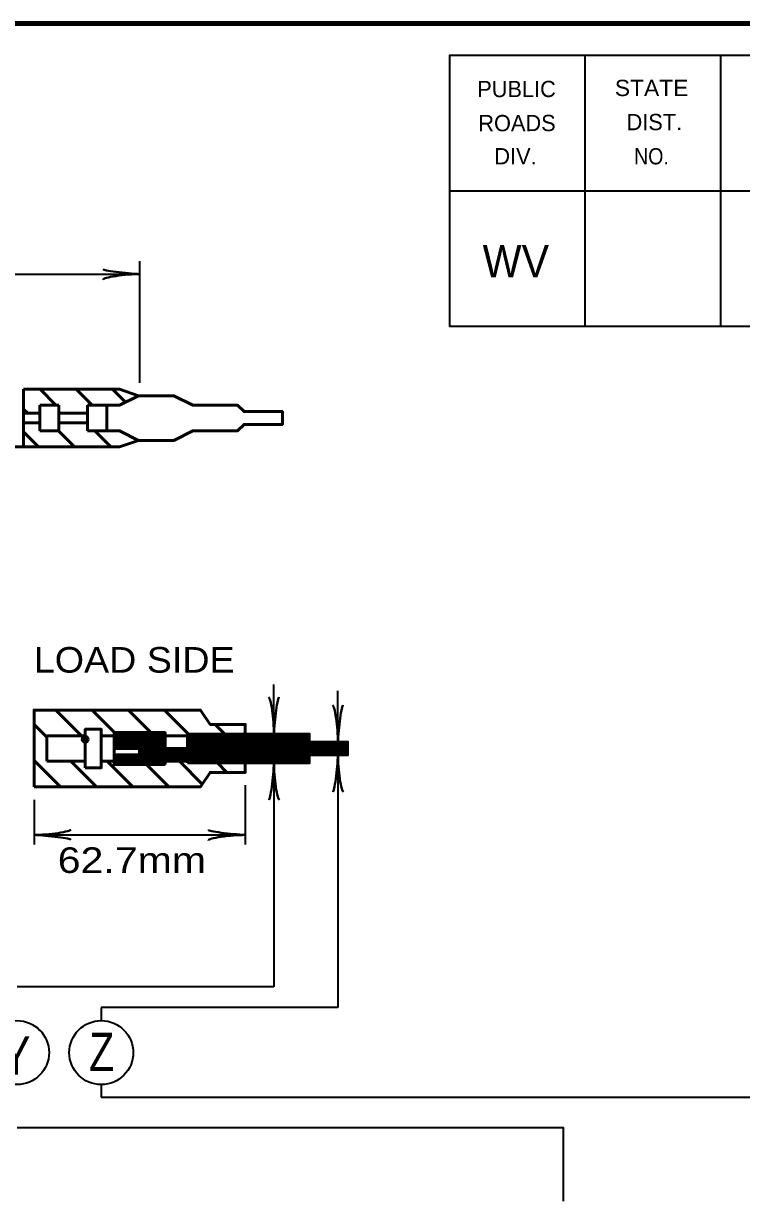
# Model space of a CAD drawing. Extents: x -32 to 824, y -6 to 538.
# Drawn here: x 637.3 to 704.6, y 421.3 to 531.7 of the extents above; entities that cross this region are included whole.
import ezdxf

# ---------------------------------------------------------------- set-up
doc = ezdxf.new("R2010")
doc.units = 0
doc.header["$LTSCALE"] = 1.1
doc.header["$PDMODE"] = 32
doc.header["$PDSIZE"] = 0.55
doc.layers.add('1', color=7, linetype='Continuous', lineweight=53)
doc.layers.add('61', color=7, linetype='Continuous', lineweight=35)

msp = doc.modelspace()

# ---------------------------------------------------------------- linework, layer by layer
at = {"layer": '1', "lineweight": 35}
for p, q in [((648.168, 498.051), (648.168, 509.451)), ((607.387, 508.251), (648.168, 508.251)), ((660.736, 465.123), (660.736, 469.773)), ((666.736, 464.373), (666.736, 469.173)), ((666.736, 463.173), (666.736, 439.473)), ((660.736, 462.423), (660.736, 441.423)), ((658.036, 460.323), (658.036, 454.773)), ((638.236, 458.973), (638.236, 454.773)), ((638.236, 455.673), (658.036, 455.673)), ((660.736, 441.423), (636.64, 441.423)), ((666.736, 439.473), (644.536, 439.473)), ((644.536, 439.473), (644.536, 438.256)), ((644.536, 432.256), (644.536, 431.073)), ((644.536, 431.073), (749.283, 431.073))]:
    msp.add_line(p, q, dxfattribs=at)
at = {"layer": '1'}
for p, q in [((637.248, 497.451), (646.264, 497.451)), ((637.26, 497.451), (637.26, 492.051)), ((640.287, 495.965), (638.802, 497.451)), ((643.696, 495.951), (642.196, 497.451)), ((646.809, 496.231), (645.59, 497.451)), ((646.264, 497.451), (648.045, 496.851)), ((638.764, 495.958), (638.764, 493.558)), ((638.764, 495.958), (640.564, 495.958)), ((640.564, 495.958), (640.564, 493.558)), ((643.264, 495.958), (643.264, 493.558)), ((643.264, 495.958), (646.264, 495.958)), ((646.264, 495.958), (648.045, 496.851)), ((648.045, 496.851), (651.345, 496.851)), ((657.325, 495.958), (657.925, 495.358)), ((637.651, 495.208), (637.258, 495.601)), ((637.26, 495.208), (638.764, 495.208)), ((640.564, 495.208), (643.264, 495.208)), ((657.925, 495.358), (661.525, 495.358)), ((661.525, 495.358), (661.525, 494.158)), ((637.26, 494.308), (638.764, 494.308)), ((640.564, 494.308), (643.264, 494.308)), ((657.325, 493.558), (657.925, 494.158)), ((657.925, 494.158), (661.525, 494.158)), ((638.649, 492.051), (637.269, 493.431)), ((638.764, 493.558), (640.564, 493.558)), ((642.043, 492.051), (640.527, 493.567)), ((643.264, 493.558), (646.264, 493.558)), ((645.437, 492.051), (643.937, 493.551)), ((646.264, 493.558), (648.045, 492.651)), ((648.045, 492.651), (646.264, 492.051)), ((648.045, 492.651), (651.345, 492.651)), ((653.125, 493.558), (657.325, 493.558)), ((630.187, 492.051), (637.275, 492.051)), ((646.264, 492.051), (637.275, 492.051)), ((642.693, 464.973), (640.293, 467.373)), ((645.787, 465.273), (643.687, 467.373)), ((649.182, 465.273), (647.082, 467.373)), ((652.726, 465.123), (650.476, 467.373)), ((639.436, 464.836), (638.236, 466.036)), ((639.436, 464.973), (639.436, 462.573)), ((639.436, 464.973), (643.036, 464.973)), ((644.536, 464.973), (645.736, 464.973)), ((645.736, 463.917), (645.736, 465.273)), ((645.736, 465.248), (645.761, 465.273)), ((645.736, 465.078), (645.931, 465.273)), ((645.736, 464.908), (646.101, 465.273)), ((645.736, 464.739), (646.27, 465.273)), ((645.736, 464.569), (646.44, 465.273)), ((645.736, 464.399), (646.61, 465.273)), ((645.736, 464.23), (646.779, 465.273)), ((645.736, 464.06), (646.949, 465.273)), ((645.736, 463.89), (647.119, 465.273)), ((647.213, 463.773), (645.736, 465.249)), ((647.043, 463.773), (645.736, 465.079)), ((645.788, 463.773), (647.288, 465.273)), ((647.383, 463.773), (645.883, 465.273)), ((645.958, 463.773), (647.458, 465.273)), ((647.552, 463.773), (646.052, 465.273)), ((646.128, 463.773), (647.628, 465.273)), ((647.722, 463.773), (646.222, 465.273)), ((646.298, 463.773), (647.798, 465.273)), ((647.892, 463.773), (646.392, 465.273)), ((646.467, 463.773), (647.967, 465.273)), ((648.061, 463.773), (646.561, 465.273)), ((646.637, 463.773), (648.137, 465.273)), ((649.731, 462.273), (646.731, 465.273)), ((646.807, 463.773), (648.307, 465.273)), ((649.901, 462.273), (646.901, 465.273)), ((646.976, 463.773), (648.476, 465.273)), ((650.07, 462.273), (647.07, 465.273)), ((647.146, 463.773), (648.646, 465.273)), ((650.24, 462.273), (647.24, 465.273)), ((647.316, 463.773), (648.816, 465.273)), ((647.343, 462.273), (650.343, 465.273)), ((650.41, 462.273), (647.41, 465.273)), ((647.486, 463.773), (648.986, 465.273)), ((647.513, 462.273), (650.513, 465.273)), ((650.536, 462.316), (647.58, 465.273)), ((647.655, 463.773), (649.155, 465.273)), ((647.683, 462.273), (650.536, 465.126)), ((650.536, 462.486), (647.749, 465.273)), ((647.825, 463.773), (649.325, 465.273)), ((647.852, 462.273), (650.536, 464.957)), ((650.536, 462.655), (647.919, 465.273)), ((647.995, 463.773), (649.495, 465.273)), ((650.536, 462.825), (648.089, 465.273)), ((648.136, 463.745), (649.664, 465.273)), ((648.136, 463.575), (649.834, 465.273)), ((648.136, 463.405), (650.004, 465.273)), ((648.136, 463.235), (650.173, 465.273)), ((650.536, 462.995), (648.258, 465.273)), ((650.536, 463.164), (648.428, 465.273)), ((650.536, 463.334), (648.598, 465.273)), ((650.536, 463.504), (648.767, 465.273)), ((650.536, 463.674), (648.937, 465.273)), ((650.536, 463.843), (649.107, 465.273)), ((650.536, 464.013), (649.277, 465.273)), ((650.536, 464.183), (649.446, 465.273)), ((650.536, 464.352), (649.616, 465.273)), ((650.536, 464.522), (649.786, 465.273)), ((650.536, 464.692), (649.955, 465.273)), ((650.536, 464.862), (650.125, 465.273)), ((650.536, 465.031), (650.295, 465.273)), ((650.536, 465.201), (650.465, 465.273)), ((650.536, 465.273), (650.536, 463.773)), ((650.536, 464.973), (652.636, 464.973)), ((652.636, 465.022), (652.737, 465.123)), ((652.636, 464.852), (652.907, 465.123)), ((652.636, 464.683), (653.076, 465.123)), ((652.636, 464.513), (653.246, 465.123)), ((652.636, 464.343), (653.416, 465.123)), ((652.636, 464.173), (653.585, 465.123)), ((652.636, 464.004), (653.755, 465.123)), ((652.636, 463.834), (653.925, 465.123)), ((652.636, 463.664), (654.095, 465.123)), ((652.636, 463.495), (654.264, 465.123)), ((652.636, 463.325), (654.434, 465.123)), ((652.636, 463.155), (654.604, 465.123)), ((652.636, 462.986), (654.773, 465.123)), ((652.636, 462.816), (654.943, 465.123)), ((652.636, 462.646), (655.113, 465.123)), ((652.636, 462.476), (655.282, 465.123)), ((655.177, 462.423), (652.636, 464.963)), ((655.346, 462.423), (652.646, 465.123)), ((652.752, 462.423), (655.452, 465.123)), ((655.516, 462.423), (652.816, 465.123)), ((652.922, 462.423), (655.622, 465.123)), ((655.686, 462.423), (652.986, 465.123)), ((653.091, 462.423), (655.792, 465.123)), ((655.855, 462.423), (653.155, 465.123)), ((653.261, 462.423), (655.961, 465.123)), ((656.025, 462.423), (653.325, 465.123)), ((653.431, 462.423), (656.131, 465.123)), ((656.195, 462.423), (653.495, 465.123)), ((653.601, 462.423), (656.301, 465.123)), ((656.364, 462.423), (653.664, 465.123)), ((653.77, 462.423), (656.47, 465.123)), ((656.534, 462.423), (653.834, 465.123)), ((653.94, 462.423), (656.64, 465.123)), ((656.704, 462.423), (654.004, 465.123)), ((654.11, 462.423), (656.81, 465.123)), ((656.874, 462.423), (654.174, 465.123)), ((654.279, 462.423), (656.98, 465.123)), ((657.043, 462.423), (654.343, 465.123)), ((654.449, 462.423), (657.149, 465.123)), ((657.213, 462.423), (654.513, 465.123)), ((654.619, 462.423), (657.319, 465.123)), ((657.383, 462.423), (654.683, 465.123)), ((654.789, 462.423), (657.489, 465.123)), ((657.552, 462.423), (654.852, 465.123)), ((654.958, 462.423), (657.658, 465.123)), ((657.722, 462.423), (655.022, 465.123)), ((655.128, 462.423), (657.828, 465.123)), ((657.892, 462.423), (655.192, 465.123)), ((656.12, 465.123), (655.22, 466.023)), ((655.298, 462.423), (657.998, 465.123)), ((658.062, 462.423), (655.361, 465.123)), ((655.467, 462.423), (658.167, 465.123)), ((658.231, 462.423), (655.531, 465.123)), ((655.637, 462.423), (658.337, 465.123)), ((658.401, 462.423), (655.701, 465.123)), ((655.807, 462.423), (658.507, 465.123)), ((658.571, 462.423), (655.871, 465.123)), ((655.976, 462.423), (658.677, 465.123)), ((658.74, 462.423), (656.04, 465.123)), ((656.146, 462.423), (658.846, 465.123)), ((658.91, 462.423), (656.21, 465.123)), ((656.316, 462.423), (659.016, 465.123)), ((659.08, 462.423), (656.38, 465.123)), ((656.486, 462.423), (659.186, 465.123)), ((659.249, 462.423), (656.549, 465.123)), ((656.655, 462.423), (659.355, 465.123)), ((659.419, 462.423), (656.719, 465.123)), ((656.825, 462.423), (659.525, 465.123)), ((659.589, 462.423), (656.889, 465.123)), ((656.995, 462.423), (659.695, 465.123)), ((659.759, 462.423), (657.058, 465.123)), ((657.164, 462.423), (659.865, 465.123)), ((659.928, 462.423), (657.228, 465.123)), ((657.334, 462.423), (660.034, 465.123)), ((660.098, 462.423), (657.398, 465.123)), ((657.504, 462.423), (660.204, 465.123)), ((660.268, 462.423), (657.568, 465.123)), ((657.674, 462.423), (660.374, 465.123)), ((660.437, 462.423), (657.737, 465.123)), ((657.843, 462.423), (660.543, 465.123)), ((660.607, 462.423), (657.907, 465.123)), ((658.013, 462.423), (660.713, 465.123)), ((660.777, 462.423), (658.077, 465.123)), ((658.183, 462.423), (660.883, 465.123)), ((660.947, 462.423), (658.247, 465.123)), ((658.352, 462.423), (661.052, 465.123)), ((661.116, 462.423), (658.416, 465.123)), ((658.522, 462.423), (661.222, 465.123)), ((661.286, 462.423), (658.586, 465.123)), ((658.692, 462.423), (661.392, 465.123)), ((661.456, 462.423), (658.756, 465.123)), ((658.861, 462.423), (661.562, 465.123)), ((661.625, 462.423), (658.925, 465.123)), ((659.031, 462.423), (661.731, 465.123)), ((661.795, 462.423), (659.095, 465.123)), ((659.201, 462.423), (661.901, 465.123)), ((661.965, 462.423), (659.265, 465.123)), ((659.371, 462.423), (662.071, 465.123)), ((662.134, 462.423), (659.434, 465.123)), ((659.54, 462.423), (662.24, 465.123)), ((662.304, 462.423), (659.604, 465.123)), ((659.71, 462.423), (662.41, 465.123)), ((662.474, 462.423), (659.774, 465.123)), ((659.88, 462.423), (662.58, 465.123)), ((662.644, 462.423), (659.944, 465.123)), ((660.05, 462.423), (662.75, 465.123)), ((662.813, 462.423), (660.113, 465.123)), ((660.219, 462.423), (662.919, 465.123)), ((662.983, 462.423), (660.283, 465.123)), ((660.389, 462.423), (663.089, 465.123)), ((663.153, 462.423), (660.453, 465.123)), ((660.559, 462.423), (663.259, 465.123)), ((663.322, 462.423), (660.622, 465.123)), ((660.728, 462.423), (663.428, 465.123)), ((663.492, 462.423), (660.792, 465.123)), ((660.898, 462.423), (663.598, 465.123)), ((663.662, 462.423), (660.962, 465.123)), ((661.068, 462.423), (663.768, 465.123)), ((663.832, 462.423), (661.132, 465.123)), ((661.237, 462.423), (663.937, 465.123)), ((664.001, 462.423), (661.301, 465.123)), ((661.407, 462.423), (664.036, 465.052)), ((664.036, 462.557), (661.471, 465.123)), ((664.036, 462.727), (661.641, 465.123)), ((664.036, 462.897), (661.81, 465.123)), ((664.036, 463.066), (661.98, 465.123)), ((664.1, 463.173), (662.15, 465.123)), ((664.269, 463.173), (662.319, 465.123)), ((664.439, 463.173), (662.489, 465.123)), ((664.609, 463.173), (662.659, 465.123)), ((664.779, 463.173), (662.829, 465.123)), ((664.948, 463.173), (662.998, 465.123)), ((665.118, 463.173), (663.168, 465.123)), ((664.036, 464.424), (663.338, 465.123)), ((664.036, 464.594), (663.507, 465.123)), ((664.036, 464.764), (663.677, 465.123)), ((664.036, 464.933), (663.847, 465.123)), ((664.036, 465.103), (664.017, 465.123)), ((646.873, 463.773), (645.736, 464.91)), ((646.704, 463.773), (645.736, 464.74)), ((646.534, 463.773), (645.736, 464.57)), ((646.364, 463.773), (645.736, 464.401)), ((646.195, 463.773), (645.736, 464.231)), ((646.025, 463.773), (645.736, 464.061)), ((645.855, 463.773), (645.736, 463.892)), ((648.022, 462.273), (650.536, 464.787)), ((648.192, 462.273), (650.536, 464.617)), ((648.361, 462.273), (650.536, 464.448)), ((648.531, 462.273), (650.536, 464.278)), ((648.701, 462.273), (650.536, 464.108)), ((648.87, 462.273), (650.536, 463.938)), ((655.007, 462.423), (652.636, 464.793)), ((654.837, 462.423), (652.636, 464.624)), ((654.667, 462.423), (652.636, 464.454)), ((654.498, 462.423), (652.636, 464.284)), ((654.328, 462.423), (652.636, 464.114)), ((654.158, 462.423), (652.636, 463.945)), ((661.577, 462.423), (664.036, 464.882)), ((661.747, 462.423), (664.036, 464.712)), ((661.916, 462.423), (664.036, 464.543)), ((662.086, 462.423), (664.036, 464.373)), ((662.256, 462.423), (664.206, 464.373)), ((662.425, 462.423), (664.375, 464.373)), ((662.595, 462.423), (664.545, 464.373)), ((662.765, 462.423), (664.715, 464.373)), ((662.935, 462.423), (664.885, 464.373)), ((663.104, 462.423), (665.054, 464.373)), ((663.274, 462.423), (665.224, 464.373)), ((665.288, 463.173), (664.088, 464.373)), ((664.194, 463.173), (665.394, 464.373)), ((665.457, 463.173), (664.257, 464.373)), ((664.363, 463.173), (665.563, 464.373)), ((665.627, 463.173), (664.427, 464.373)), ((664.533, 463.173), (665.733, 464.373)), ((665.797, 463.173), (664.597, 464.373)), ((664.703, 463.173), (665.903, 464.373)), ((665.966, 463.173), (664.767, 464.373)), ((664.872, 463.173), (666.072, 464.373)), ((666.136, 463.173), (664.936, 464.373)), ((665.042, 463.173), (666.242, 464.373)), ((666.306, 463.173), (665.106, 464.373)), ((665.212, 463.173), (666.412, 464.373)), ((666.476, 463.173), (665.276, 464.373)), ((665.382, 463.173), (666.582, 464.373)), ((666.645, 463.173), (665.445, 464.373)), ((665.551, 463.173), (666.751, 464.373)), ((666.815, 463.173), (665.615, 464.373)), ((665.721, 463.173), (666.921, 464.373)), ((666.985, 463.173), (665.785, 464.373)), ((665.891, 463.173), (667.091, 464.373)), ((667.154, 463.173), (665.954, 464.373)), ((666.06, 463.173), (667.26, 464.373)), ((667.324, 463.173), (666.124, 464.373)), ((666.23, 463.173), (667.43, 464.373)), ((667.494, 463.173), (666.294, 464.373)), ((666.4, 463.173), (667.6, 464.373)), ((667.636, 463.2), (666.464, 464.373)), ((666.57, 463.173), (667.636, 464.239)), ((667.636, 463.37), (666.633, 464.373)), ((666.739, 463.173), (667.636, 464.07)), ((667.636, 463.539), (666.803, 464.373)), ((666.909, 463.173), (667.636, 463.9)), ((667.636, 463.709), (666.973, 464.373)), ((667.636, 463.879), (667.142, 464.373)), ((667.636, 464.049), (667.312, 464.373)), ((667.636, 464.218), (667.482, 464.373)), ((645.736, 463.173), (645.736, 463.773)), ((645.736, 463.042), (645.867, 463.173)), ((645.736, 462.872), (646.037, 463.173)), ((645.736, 462.702), (646.207, 463.173)), ((645.736, 462.533), (646.376, 463.173)), ((645.736, 462.363), (646.546, 463.173)), ((646.507, 462.273), (645.736, 463.043)), ((646.337, 462.273), (645.736, 462.873)), ((646.676, 462.273), (645.776, 463.173)), ((645.816, 462.273), (646.716, 463.173)), ((646.846, 462.273), (645.946, 463.173)), ((645.986, 462.273), (646.885, 463.173)), ((647.016, 462.273), (646.116, 463.173)), ((646.155, 462.273), (647.055, 463.173)), ((647.185, 462.273), (646.285, 463.173)), ((646.325, 462.273), (647.225, 463.173)), ((647.355, 462.273), (646.455, 463.173)), ((646.495, 462.273), (647.395, 463.173)), ((647.525, 462.273), (646.625, 463.173)), ((646.664, 462.273), (647.564, 463.173)), ((647.695, 462.273), (646.795, 463.173)), ((646.834, 462.273), (647.734, 463.173)), ((647.864, 462.273), (646.964, 463.173)), ((647.004, 462.273), (647.904, 463.173)), ((648.034, 462.273), (647.134, 463.173)), ((647.173, 462.273), (648.073, 463.173)), ((648.204, 462.273), (647.304, 463.173)), ((648.373, 462.273), (647.473, 463.173)), ((648.543, 462.273), (647.643, 463.173)), ((648.713, 462.273), (647.813, 463.173)), ((648.883, 462.273), (647.983, 463.173)), ((649.561, 462.273), (648.136, 463.698)), ((649.392, 462.273), (648.136, 463.528)), ((649.222, 462.273), (648.136, 463.358)), ((649.052, 462.273), (648.136, 463.189)), ((649.04, 462.273), (650.536, 463.769)), ((649.21, 462.273), (650.536, 463.599)), ((649.38, 462.273), (650.536, 463.429)), ((649.549, 462.273), (650.536, 463.26)), ((649.719, 462.273), (650.536, 463.09)), ((649.889, 462.273), (650.536, 462.92)), ((650.058, 462.273), (650.536, 462.75)), ((650.536, 463.754), (650.555, 463.773)), ((650.536, 463.584), (650.725, 463.773)), ((650.536, 463.414), (650.895, 463.773)), ((650.536, 463.244), (651.064, 463.773)), ((650.536, 463.075), (651.234, 463.773)), ((650.536, 462.905), (651.404, 463.773)), ((650.536, 462.735), (651.574, 463.773)), ((651.568, 462.573), (650.536, 463.604)), ((651.398, 462.573), (650.536, 463.435)), ((651.229, 462.573), (650.536, 463.265)), ((651.059, 462.573), (650.536, 463.095)), ((650.889, 462.573), (650.536, 462.925)), ((650.719, 462.573), (650.536, 462.756)), ((651.738, 462.573), (650.538, 463.773)), ((650.543, 462.573), (651.743, 463.773)), ((651.907, 462.573), (650.707, 463.773)), ((650.713, 462.573), (651.913, 463.773)), ((652.077, 462.573), (650.877, 463.773)), ((650.883, 462.573), (652.083, 463.773)), ((652.247, 462.573), (651.047, 463.773)), ((651.052, 462.573), (652.252, 463.773)), ((652.416, 462.573), (651.216, 463.773)), ((651.222, 462.573), (652.422, 463.773)), ((652.586, 462.573), (651.386, 463.773)), ((651.392, 462.573), (652.592, 463.773)), ((652.636, 462.692), (651.556, 463.773)), ((651.562, 462.573), (652.636, 463.647)), ((652.636, 462.862), (651.726, 463.773)), ((651.731, 462.573), (652.636, 463.478)), ((652.636, 463.032), (651.895, 463.773)), ((651.901, 462.573), (652.636, 463.308)), ((652.636, 463.201), (652.065, 463.773)), ((652.071, 462.573), (652.636, 463.138)), ((652.636, 463.371), (652.235, 463.773)), ((652.24, 462.573), (652.636, 462.969)), ((652.636, 463.541), (652.404, 463.773)), ((652.41, 462.573), (652.636, 462.799)), ((652.636, 463.711), (652.574, 463.773)), ((653.989, 462.423), (652.636, 463.775)), ((652.636, 462.423), (652.636, 463.773)), ((653.819, 462.423), (652.636, 463.605)), ((653.649, 462.423), (652.636, 463.436)), ((653.479, 462.423), (652.636, 463.266)), ((653.31, 462.423), (652.636, 463.096)), ((653.14, 462.423), (652.636, 462.926)), ((652.97, 462.423), (652.636, 462.757)), ((663.444, 462.423), (664.036, 463.015)), ((663.613, 462.423), (664.036, 462.846)), ((667.079, 463.173), (667.636, 463.73)), ((667.248, 463.173), (667.636, 463.561)), ((667.418, 463.173), (667.636, 463.391)), ((667.588, 463.173), (667.636, 463.221)), ((640.705, 460.173), (638.236, 462.641)), ((639.436, 462.573), (643.036, 462.573)), ((644.099, 460.173), (641.699, 462.573)), ((644.536, 462.573), (645.736, 462.573)), ((647.493, 460.173), (645.093, 462.573)), ((646.167, 462.273), (645.736, 462.704)), ((645.998, 462.273), (645.736, 462.534)), ((645.828, 462.273), (645.736, 462.364)), ((650.887, 460.173), (648.787, 462.273)), ((650.228, 462.273), (650.536, 462.581)), ((650.398, 462.273), (650.536, 462.411)), ((650.55, 462.573), (650.536, 462.586)), ((650.536, 462.573), (650.536, 462.273)), ((654.014, 460.44), (651.882, 462.573)), ((652.58, 462.573), (652.636, 462.629)), ((652.801, 462.423), (652.636, 462.587)), ((656.326, 461.523), (655.426, 462.423)), ((663.783, 462.423), (664.036, 462.676)), ((663.953, 462.423), (664.036, 462.506))]:
    msp.add_line(p, q, dxfattribs=at)
at = {"layer": '1', "lineweight": 158}
msp.add_lwpolyline([(817.398, 531.744), (25.698, 531.644), (25.798, 5.644)], dxfattribs=at)
at = {"layer": '1'}
for points in [[(637.275, 492.051), (632.753, 492.051), (632.753, 495.958)], [(651.345, 496.851), (653.125, 495.958), (657.325, 495.958)], [(638.236, 460.173), (638.236, 467.373), (653.836, 467.373), (654.736, 466.023), (658.036, 466.023), (658.036, 465.123)], [(645.736, 463.173), (645.736, 463.773), (645.736, 465.273), (650.536, 465.273)], [(650.536, 462.273), (645.736, 462.273), (645.736, 463.173), (648.136, 463.173), (648.136, 463.773), (645.736, 463.773)], [(658.036, 462.423), (658.036, 461.523), (654.736, 461.523), (653.836, 460.173), (638.236, 460.173)]]:
    msp.add_lwpolyline(points, dxfattribs=at)
for points in [[(645.064, 493.558), (645.064, 495.958), (646.264, 495.958), (648.045, 496.851), (651.345, 496.851), (653.125, 495.958), (657.325, 495.958), (657.925, 495.358), (661.525, 495.358), (661.525, 494.158), (657.925, 494.158), (657.325, 493.558), (653.125, 493.558), (651.345, 492.651), (648.045, 492.651), (646.264, 493.558)], [(643.036, 461.973), (643.036, 465.573), (644.536, 465.573), (644.536, 461.973)], [(643.036, 461.973), (643.036, 465.573), (644.536, 465.573), (644.536, 461.973)], [(652.636, 462.423), (652.636, 462.573), (652.636, 463.773), (652.636, 465.123), (664.036, 465.123), (664.036, 464.373), (667.636, 464.373), (667.636, 463.173), (664.036, 463.173), (664.036, 462.423)], [(650.536, 462.573), (650.536, 463.773), (652.636, 463.773), (652.636, 462.573)]]:
    msp.add_lwpolyline(points, close=True, dxfattribs=at)
at = {"layer": '1', "lineweight": 35}
msp.add_lwpolyline([(636.64, 428.223), (687.841, 428.223), (687.841, 421.316)], dxfattribs=at)
for centre in [(636.64, 435.256), (644.536, 435.256)]:
    msp.add_circle(centre, 3, dxfattribs=at)
at = {"layer": '1', "lineweight": 40}
for centre, major_axis, ratio, start_param, end_param in [((646.858, 507.919), (2.143, 0.187), 0.122415, 0.8963533, 3.1415927), ((646.823, 508.505), (2.108, -0.211), 0.07063, 3.1407148, 5.41811), ((660.405, 466.432), (0.187, -2.143), 0.122415, 0.8963533, 3.1415927), ((660.405, 466.432), (0.187, -2.143), 0.122415, 0.8963533, 3.1415927), ((660.99, 466.467), (-0.211, -2.108), 0.07063, 3.1407148, 5.41811), ((660.99, 466.467), (-0.211, -2.108), 0.07063, 3.1407148, 5.41811), ((666.405, 465.682), (0.187, -2.143), 0.122415, 0.8963533, 3.1415927), ((666.99, 465.717), (-0.211, -2.108), 0.07063, 3.1407148, 5.41811), ((666.482, 461.828), (0.211, 2.108), 0.07063, 3.1407148, 5.41811), ((667.068, 461.863), (-0.187, 2.143), 0.122415, 0.8963533, 3.1415927), ((660.482, 461.078), (0.211, 2.108), 0.07063, 3.1407148, 5.41811), ((660.482, 461.078), (0.211, 2.108), 0.07063, 3.1407148, 5.41811), ((661.068, 461.113), (-0.187, 2.143), 0.122415, 0.8963533, 3.1415927), ((661.068, 461.113), (-0.187, 2.143), 0.122415, 0.8963533, 3.1415927), ((639.546, 456.004), (-2.143, -0.187), 0.122415, 0.8963533, 3.1415927), ((639.546, 456.004), (-2.143, -0.187), 0.122415, 0.8963533, 3.1415927), ((656.692, 455.927), (2.108, -0.211), 0.07063, 3.1407148, 5.41811), ((639.581, 455.419), (-2.108, 0.211), 0.07063, 3.1407148, 5.41811), ((639.581, 455.419), (-2.108, 0.211), 0.07063, 3.1407148, 5.41811), ((656.727, 455.341), (2.143, 0.187), 0.122415, 0.8963533, 3.1415927)]:
    msp.add_ellipse(centre, major_axis=major_axis, ratio=ratio, start_param=start_param, end_param=end_param, dxfattribs=at)
at = {"layer": '1'}
msp.add_point((643.036, 464.63), dxfattribs=at)
at = {"layer": '61'}
for p, q in [((689.898, 528.744), (689.898, 503.344)), ((702.598, 528.744), (702.598, 503.344)), ((814.298, 516.044), (677.198, 516.044))]:
    msp.add_line(p, q, dxfattribs=at)
for points in [[(814.298, 528.744), (677.198, 528.744), (677.198, 503.344)], [(814.298, 528.744), (814.298, 503.344), (677.198, 503.344)]]:
    msp.add_lwpolyline(points, dxfattribs=at)

# ---------------------------------------------------------------- texts
at = {"layer": '1'}
for s, height, width, p in [('WV', 3.048, 0.95, (680.298, 507.944)), ('LOAD SIDE', 2.4, 1.1, (638.215, 470.885)), ('62.7mm', 2.4, 1.2, (640.457, 452.104)), ('Y', 3.6, 0.85, (635.18, 433.191)), ('Z', 3.6, 0.8, (643.396, 433.519))]:
    msp.add_text(s, height=height, dxfattribs=dict(at, width=width)).set_placement(p)
at = {"layer": '61'}
for s, rotation, p in [('PUBLIC', 0.033, (679.798, 524.844)), ('ROADS', 0.124, (679.898, 521.644)), ('DIST.', 0.056, (693.798, 521.744)), ('DIV.', 359.932, (681.398, 518.544))]:
    msp.add_text(s, height=1.525, rotation=rotation, dxfattribs=at).set_placement(p)
for s, rotation, width, p in [('STATE', 0.059, 1.05, (692.698, 524.944)), ('NO.', 359.852, 0.9, (694.498, 518.544))]:
    msp.add_text(s, height=1.525, rotation=rotation, dxfattribs=dict(at, width=width)).set_placement(p)

doc.saveas('drawing.dxf')
